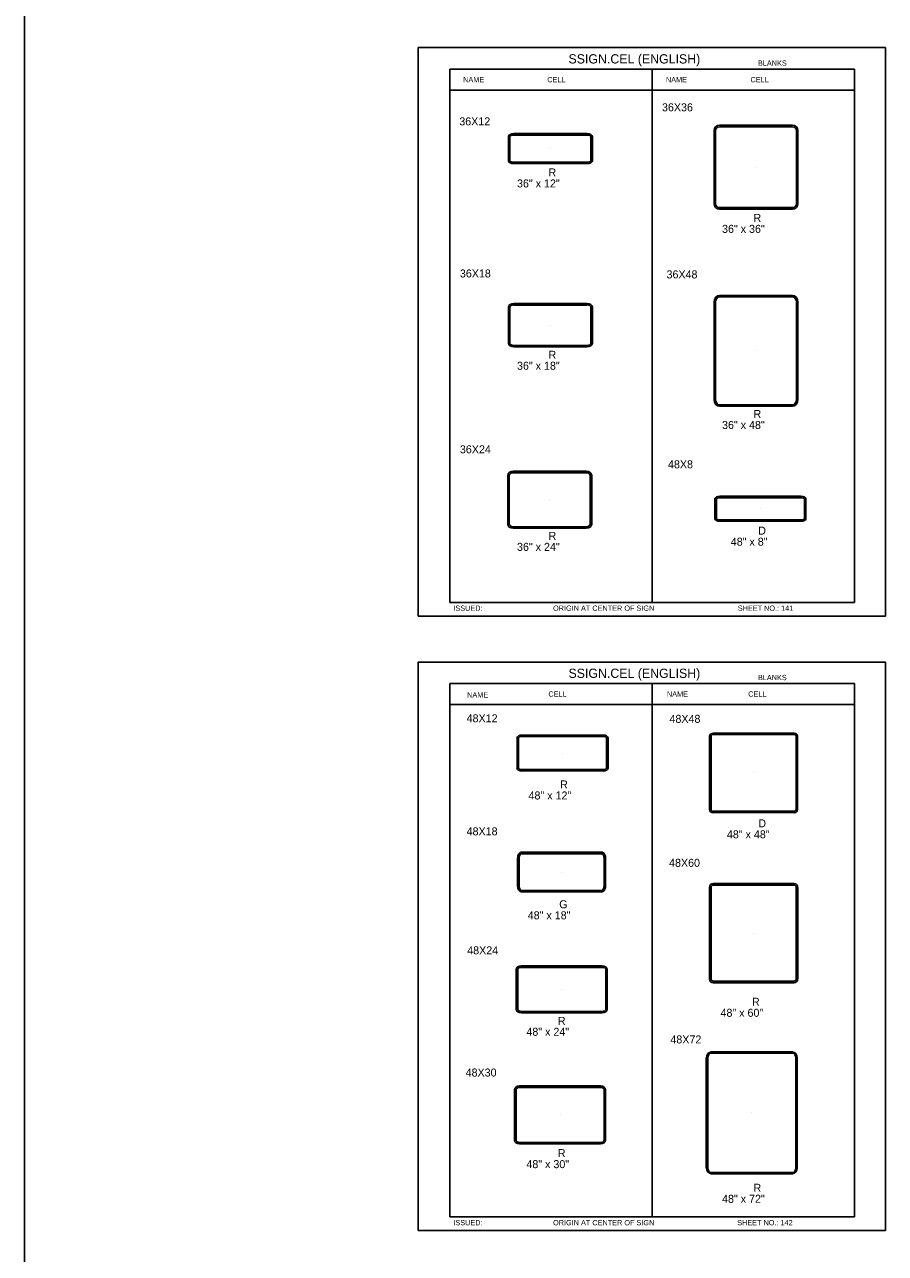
# Model space of a CAD drawing. Extents: x -5299 to 22597, y -19549 to -1808.
# Drawn here: x -218 to 1073, y -17521 to -15678 of the extents above; entities that cross this region are included whole.
import ezdxf

# ---------------------------------------------------------------- set-up
doc = ezdxf.new("R2010")
doc.units = 0
for name, color, linetype in [('Level 1', 7, 'Continuous'), ('Level 2', 7, 'Continuous'), ('Level 3', 7, 'Continuous'), ('Level 60', 7, 'Continuous')]:
    doc.layers.add(name, color=color, linetype=linetype)

msp = doc.modelspace()

# ---------------------------------------------------------------- linework, layer by layer
at = {"layer": 'Level 1'}
for p, q in [((1026.8, -15744.9), (419.8, -15744.9)), ((419.8, -15744.9), (419.8, -16544.9)), ((723.3, -15744.9), (723.3, -16544.9)), ((1026.8, -15744.9), (1026.8, -16544.9)), ((1026.8, -15776.5), (419.8, -15776.5)), ((570.7, -15864.2), (570.7, -15864.2)), ((879.1, -15892), (879.1, -15892)), ((570.7, -16129), (570.7, -16129)), ((879.1, -16167.5), (879.1, -16167.5)), ((569.7, -16390.8), (569.7, -16390.8)), ((885.8, -16404.3), (885.8, -16404.3)), ((419.8, -16544.9), (1026.8, -16544.9)), ((1026.8, -16666.3), (419.8, -16666.3)), ((419.8, -16666.3), (419.8, -17466.3)), ((723.3, -16666.3), (723.3, -17466.3)), ((1026.8, -16666.3), (1026.8, -17466.3)), ((1026.8, -16697.9), (419.8, -16697.9)), ((588.9, -16770.6), (588.9, -16770.6)), ((875.5, -16800.4), (875.5, -16800.4)), ((587.5, -16949), (587.5, -16949)), ((875.6, -17040.7), (875.6, -17040.7)), ((587.7, -17125), (587.7, -17125)), ((585.1, -17313.3), (585.1, -17313.3)), ((872.9, -17310.1), (872.9, -17310.1)), ((419.8, -17466.3), (1026.8, -17466.3))]:
    msp.add_line(p, q, dxfattribs=at)
at = {"layer": 'Level 3'}
for p, q in [((-218.2, -11251.9), (-218.2, -19549.4)), ((933.9, -15829.1), (824.3, -15829.1)), ((507.8, -15845.9), (507.8, -15882.5)), ((510, -15845.9), (510, -15882.5)), ((625.5, -15841.7), (515.9, -15841.7)), ((625.5, -15844), (515.9, -15844)), ((631.4, -15882.5), (631.4, -15845.9)), ((633.6, -15882.5), (633.6, -15845.9)), ((816.2, -15837.2), (816.2, -15946.8)), ((818.4, -15837.2), (818.4, -15946.8)), ((933.9, -15831.3), (824.3, -15831.3)), ((939.9, -15946.8), (939.9, -15837.2)), ((942.1, -15946.8), (942.1, -15837.2)), ((515.9, -15884.4), (625.5, -15884.4)), ((515.9, -15886.7), (625.5, -15886.7)), ((824.3, -15952.7), (933.9, -15952.7)), ((824.3, -15954.9), (933.9, -15954.9)), ((933.9, -16084.3), (824.3, -16084.3)), ((933.9, -16086.5), (824.3, -16086.5)), ((507.8, -16101.6), (507.8, -16156.4)), ((510, -16101.6), (510, -16156.4)), ((625.5, -16096.5), (515.9, -16096.5)), ((625.5, -16098.7), (515.9, -16098.7)), ((631.4, -16156.4), (631.4, -16101.6)), ((633.6, -16156.4), (633.6, -16101.6)), ((816.2, -16094.4), (816.2, -16240.5)), ((818.4, -16094.4), (818.4, -16240.5)), ((939.9, -16240.5), (939.9, -16094.4)), ((942.1, -16240.5), (942.1, -16094.4)), ((515.9, -16159.4), (625.5, -16159.4)), ((515.9, -16161.6), (625.5, -16161.6)), ((824.3, -16248.4), (933.9, -16248.4)), ((824.3, -16250.6), (933.9, -16250.6)), ((506.7, -16354.2), (506.7, -16427.3)), ((508.9, -16354.2), (508.9, -16427.3)), ((624.5, -16348.1), (514.8, -16348.1)), ((624.5, -16350.3), (514.8, -16350.3)), ((630.4, -16427.3), (630.4, -16354.2)), ((632.6, -16427.3), (632.6, -16354.2)), ((817.6, -16389.1), (817.6, -16419.5)), ((819.8, -16389.1), (819.8, -16419.5)), ((946.6, -16385.6), (825, -16385.6)), ((946.6, -16387.8), (825, -16387.8)), ((951.9, -16419.5), (951.9, -16389.1)), ((954.1, -16419.5), (954.1, -16389.1)), ((514.8, -16431.2), (624.5, -16431.2)), ((514.8, -16433.5), (624.5, -16433.5)), ((825, -16420.8), (946.6, -16420.8)), ((825, -16423), (946.6, -16423)), ((520.6, -16747.8), (520.6, -16793.4)), ((522.8, -16747.8), (522.8, -16793.4)), ((649.7, -16743.6), (528, -16743.6)), ((649.7, -16745.8), (528, -16745.8)), ((654.9, -16793.4), (654.9, -16747.8)), ((657.1, -16793.4), (657.1, -16747.8)), ((809.5, -16745.5), (809.5, -16855.3)), ((811.7, -16745.5), (811.7, -16855.3)), ((936.3, -16740.8), (814.7, -16740.8)), ((936.3, -16742.8), (814.7, -16742.8)), ((939.3, -16855.3), (939.3, -16745.5)), ((941.5, -16855.3), (941.5, -16745.5)), ((528, -16795.3), (649.7, -16795.3)), ((528, -16797.5), (649.7, -16797.5)), ((814.7, -16858), (936.3, -16858)), ((814.7, -16860), (936.3, -16860)), ((521.5, -16969), (521.5, -16929.1)), ((523.7, -16969), (523.7, -16929.1)), ((526.7, -16919.4), (648.3, -16919.4)), ((526.7, -16921.6), (648.3, -16921.6)), ((651.3, -16929.1), (651.3, -16969)), ((653.5, -16929.1), (653.5, -16969)), ((809.6, -16972.1), (809.6, -17109.3)), ((811.8, -16972.1), (811.8, -17109.3)), ((936.4, -16966.2), (814.8, -16966.2)), ((936.4, -16968.7), (814.8, -16968.7)), ((939.5, -17109.3), (939.5, -16972.1)), ((941.7, -17109.3), (941.7, -16972.1)), ((648.3, -16976.5), (526.7, -16976.5)), ((648.3, -16978.7), (526.7, -16978.7)), ((519.5, -17094.6), (519.5, -17155.4)), ((521.7, -17094.6), (521.7, -17155.4)), ((648.5, -17089.8), (526.9, -17089.8)), ((648.5, -17092), (526.9, -17092)), ((653.7, -17155.4), (653.7, -17094.6)), ((655.9, -17155.4), (655.9, -17094.6)), ((814.8, -17112.7), (936.4, -17112.7)), ((814.8, -17115.1), (936.4, -17115.1)), ((526.9, -17158), (648.5, -17158)), ((526.9, -17160.2), (648.5, -17160.2)), ((804.6, -17227.8), (804.6, -17392.4)), ((806.8, -17227.8), (806.8, -17392.4)), ((933.7, -17218.7), (812.1, -17218.7)), ((933.7, -17220.7), (812.1, -17220.7)), ((938.9, -17392.4), (938.9, -17227.8)), ((941.1, -17392.4), (941.1, -17227.8)), ((516.9, -17275.3), (516.9, -17351.3)), ((519.1, -17275.3), (519.1, -17351.3)), ((646, -17269.8), (524.3, -17269.8)), ((646, -17272.1), (524.3, -17272.1)), ((651.2, -17351.3), (651.2, -17275.3)), ((653.4, -17351.3), (653.4, -17275.3)), ((524.3, -17354.6), (646, -17354.6)), ((524.3, -17356.8), (646, -17356.8)), ((812.1, -17399.5), (933.7, -17399.5)), ((812.1, -17401.5), (933.7, -17401.5))]:
    msp.add_line(p, q, dxfattribs=at)
for centre, radius, start, end in [((824.3, -15837.2), 8.12, 90, 180), ((933.9, -15837.2), 8.12, 0, 90), ((824.3, -15837.2), 5.91, 90, 180), ((933.9, -15837.2), 5.91, 0, 90), ((824.3, -15946.8), 8.12, 180, 270), ((824.3, -15946.8), 5.91, 180, 270), ((933.9, -15946.8), 5.91, 270, 0), ((933.9, -15946.8), 8.12, 270, 0)]:
    msp.add_arc(centre, radius, start, end, dxfattribs=at)
for centre, major_axis, ratio, start_param, end_param in [((515.9, -15845.9), (-8.12, 0), 0.514853, 4.712389, 6.283185), ((515.9, -15845.9), (-5.91, 0), 0.333333, 4.712389, 6.283185), ((625.5, -15845.9), (-8.12, 0), 0.514853, 3.141593, 4.712389), ((625.5, -15845.9), (-5.91, 0), 0.333333, 3.141593, 4.712389), ((515.9, -15882.5), (8.12, 0), 0.514853, 3.141593, 4.712389), ((515.9, -15882.5), (5.91, 0), 0.333333, 3.141593, 4.712389), ((625.5, -15882.5), (5.91, 0), 0.333333, 4.712389, 6.283185), ((625.5, -15882.5), (8.12, 0), 0.514853, 4.712389, 6.283185), ((824.3, -16094.4), (0, -10.1), 0.804782, 3.141593, 4.712389), ((824.3, -16094.4), (0, -7.88), 0.75, 3.141593, 4.712389), ((933.9, -16094.4), (0, 10.1), 0.804782, 4.712389, 6.283185), ((933.9, -16094.4), (0, 7.88), 0.75, 4.712389, 6.283185), ((515.9, -16101.6), (-8.12, 0), 0.63614, 4.712389, 6.283185), ((515.9, -16101.6), (-5.91, 0), 0.5, 4.712389, 6.283185), ((625.5, -16101.6), (-8.12, 0), 0.63614, 3.141593, 4.712389), ((625.5, -16101.6), (-5.91, 0), 0.5, 3.141593, 4.712389), ((515.9, -16156.4), (8.12, 0), 0.63614, 3.141593, 4.712389), ((515.9, -16156.4), (5.91, 0), 0.5, 3.141593, 4.712389), ((625.5, -16156.4), (5.91, 0), 0.5, 4.712389, 6.283185), ((625.5, -16156.4), (8.12, 0), 0.63614, 4.712389, 6.283185), ((824.3, -16240.5), (0, -10.1), 0.804782, 4.712389, 6.283185), ((824.3, -16240.5), (0, -7.88), 0.75, 4.712389, 6.283185), ((933.9, -16240.5), (0, 7.88), 0.75, 3.141593, 4.712389), ((933.9, -16240.5), (0, 10.1), 0.804782, 3.141593, 4.712389), ((514.8, -16354.2), (-8.12, 0), 0.757427, 4.712389, 6.283185), ((514.8, -16354.2), (-5.91, 0), 0.666667, 4.712389, 6.283185), ((624.5, -16354.2), (-8.12, 0), 0.757427, 3.141593, 4.712389), ((624.5, -16354.2), (-5.91, 0), 0.666667, 3.141593, 4.712389), ((825, -16389.1), (-7.43, 0), 0.473248, 4.712389, 6.283185), ((825, -16389.1), (-5.22, 0), 0.25, 4.712389, 6.283185), ((946.6, -16389.1), (-7.43, 0), 0.473248, 3.141593, 4.712389), ((946.6, -16389.1), (-5.22, 0), 0.25, 3.141593, 4.712389), ((825, -16419.5), (7.43, 0), 0.473248, 3.141593, 4.712389), ((825, -16419.5), (5.22, 0), 0.25, 3.141593, 4.712389), ((946.6, -16419.5), (5.22, 0), 0.25, 4.712389, 6.283185), ((946.6, -16419.5), (7.43, 0), 0.473248, 4.712389, 6.283185), ((514.8, -16427.3), (8.12, 0), 0.757427, 3.141593, 4.712389), ((514.8, -16427.3), (5.91, 0), 0.666667, 3.141593, 4.712389), ((624.5, -16427.3), (5.91, 0), 0.666667, 4.712389, 6.283185), ((624.5, -16427.3), (8.12, 0), 0.757427, 4.712389, 6.283185), ((528, -16747.8), (-7.43, 0), 0.56104, 4.712389, 6.283185), ((528, -16747.8), (-5.22, 0), 0.375, 4.712389, 6.283185), ((649.7, -16747.8), (-7.43, 0), 0.56104, 3.141593, 4.712389), ((649.7, -16747.8), (-5.22, 0), 0.375, 3.141593, 4.712389), ((814.7, -16745.5), (-5.22, 0), 0.9025, 4.712389, 6.283185), ((814.7, -16745.5), (-3.01, 0), 0.9025, 4.712389, 6.283185), ((936.3, -16745.5), (-5.22, 0), 0.9025, 3.141593, 4.712389), ((936.3, -16745.5), (-3.01, 0), 0.9025, 3.141593, 4.712389), ((528, -16793.4), (7.43, 0), 0.56104, 3.141593, 4.712389), ((528, -16793.4), (5.22, 0), 0.375, 3.141593, 4.712389), ((649.7, -16793.4), (5.22, 0), 0.375, 4.712389, 6.283185), ((649.7, -16793.4), (7.43, 0), 0.56104, 4.712389, 6.283185), ((814.7, -16855.3), (5.22, 0), 0.9025, 3.141593, 4.712389), ((814.7, -16855.3), (3.01, 0), 0.9025, 3.141593, 4.712389), ((936.3, -16855.3), (3.01, 0), 0.9025, 4.712389, 6.283185), ((936.3, -16855.3), (5.22, 0), 0.9025, 4.712389, 6.283185), ((526.7, -16929.1), (0, -9.73), 0.536402, 3.141593, 4.712389), ((526.7, -16929.1), (0, -7.52), 0.4, 3.141593, 4.712389), ((648.3, -16929.1), (0, 9.73), 0.536402, 4.712389, 6.283185), ((648.3, -16929.1), (0, 7.52), 0.4, 4.712389, 6.283185), ((526.7, -16969), (0, -9.73), 0.536402, 4.712389, 6.283185), ((526.7, -16969), (0, -7.52), 0.4, 4.712389, 6.283185), ((648.3, -16969), (0, 7.52), 0.4, 3.141593, 4.712389), ((648.3, -16969), (0, 9.73), 0.536402, 3.141593, 4.712389), ((814.8, -16972.1), (0, -5.89), 0.886427, 3.141593, 4.712389), ((814.8, -16972.1), (0, -3.39), 0.886427, 3.141593, 4.712389), ((936.4, -16972.1), (0, 5.89), 0.886427, 4.712389, 6.283185), ((936.4, -16972.1), (0, 3.39), 0.886427, 4.712389, 6.283185), ((526.9, -17094.6), (-7.43, 0), 0.648832, 4.712389, 6.283185), ((526.9, -17094.6), (-5.22, 0), 0.5, 4.712389, 6.283185), ((648.5, -17094.6), (-7.43, 0), 0.648832, 3.141593, 4.712389), ((648.5, -17094.6), (-5.22, 0), 0.5, 3.141593, 4.712389), ((814.8, -17109.3), (0, -5.89), 0.886427, 4.712389, 6.283185), ((814.8, -17109.3), (0, -3.39), 0.886427, 4.712389, 6.283185), ((936.4, -17109.3), (0, 3.39), 0.886427, 3.141593, 4.712389), ((936.4, -17109.3), (0, 5.89), 0.886427, 3.141593, 4.712389), ((526.9, -17155.4), (7.43, 0), 0.648832, 3.141593, 4.712389), ((526.9, -17155.4), (5.22, 0), 0.5, 3.141593, 4.712389), ((648.5, -17155.4), (5.22, 0), 0.5, 4.712389, 6.283185), ((648.5, -17155.4), (7.43, 0), 0.648832, 4.712389, 6.283185), ((812.1, -17227.8), (0, -9.06), 0.820056, 3.141593, 4.712389), ((812.1, -17227.8), (0, -7.07), 0.738689, 3.141593, 4.712389), ((933.7, -17227.8), (0, 9.06), 0.820056, 4.712389, 6.283185), ((933.7, -17227.8), (0, 7.07), 0.738689, 4.712389, 6.283185), ((524.3, -17275.3), (-7.43, 0), 0.736624, 4.712389, 6.283185), ((524.3, -17275.3), (-5.22, 0), 0.625, 4.712389, 6.283185), ((646, -17275.3), (-7.43, 0), 0.736624, 3.141593, 4.712389), ((646, -17275.3), (-5.22, 0), 0.625, 3.141593, 4.712389), ((524.3, -17351.3), (7.43, 0), 0.736624, 3.141593, 4.712389), ((524.3, -17351.3), (5.22, 0), 0.625, 3.141593, 4.712389), ((646, -17351.3), (5.22, 0), 0.625, 4.712389, 6.283185), ((646, -17351.3), (7.43, 0), 0.736624, 4.712389, 6.283185), ((812.1, -17392.4), (0, -9.06), 0.820056, 4.712389, 6.283185), ((812.1, -17392.4), (0, -7.07), 0.738689, 4.712389, 6.283185), ((933.7, -17392.4), (0, 7.07), 0.738689, 3.141593, 4.712389), ((933.7, -17392.4), (0, 9.06), 0.820056, 3.141593, 4.712389)]:
    msp.add_ellipse(centre, major_axis=major_axis, ratio=ratio, start_param=start_param, end_param=end_param, dxfattribs=at)
at = {"layer": 'Level 60'}
for points in [[(372.3, -16565.1), (1073.3, -16565.1), (1073.3, -15712.7), (372.3, -15712.7)], [(372.3, -17486.5), (1073.3, -17486.5), (1073.3, -16634.1), (372.3, -16634.1)]]:
    msp.add_lwpolyline(points, close=True, dxfattribs=at)

# ---------------------------------------------------------------- texts
at = {"layer": 'Level 2'}
for s, p in [('36X36', (738.1, -15808.2)), ('36X12', (434, -15829.3)), ('36X18', (434.9, -16057.4)), ('36X48', (744.9, -16058.8)), ('36X24', (434.9, -16321.1)), ('48X8', (747.1, -16343.6)), ('48X12', (445, -16724.5)), ('48X48', (749.3, -16725.3)), ('48X18', (445, -16894)), ('48X60', (748.7, -16941.2)), ('48X24', (445.9, -17072.5)), ('48X72', (750.7, -17206.1)), ('48X30', (443.5, -17255.7))]:
    msp.add_text(s, height=12, dxfattribs=at).set_placement(p)
at = {"layer": 'Level 3'}
for s, height, p in [('SSIGN.CEL (ENGLISH)', 13.857, (597.8, -15736.5)), ('BLANKS', 7.92, (882.1, -15739.9)), ('NAME', 7.92, (439.8, -15764.7)), ('CELL', 7.92, (566, -15764.7)), ('NAME', 7.92, (744, -15764.7)), ('CELL', 7.92, (870.9, -15764.7)), ('R', 12, (567.9, -15905.9)), ('36" x 12"', 12, (520.6, -15922.4)), ('R', 12, (875.4, -15974.1)), ('36" x 36"', 12, (828.2, -15990.5)), ('R', 12, (567.9, -16179.3)), ('36" x 18"', 12, (520.6, -16195.8)), ('R', 12, (875.4, -16268.1)), ('36" x 48"', 12, (828.2, -16284.6)), ('D', 12, (882.5, -16443.1)), ('36" x 24"', 12, (520.6, -16467.4)), ('R', 12, (567.9, -16450.9)), ('48" x 8"', 12, (841.3, -16459.6)), ('ISSUED:', 7.92, (425.1, -16557.3)), ('ORIGIN AT CENTER OF SIGN', 7.918, (574.7, -16557.3)), ('SHEET NO.: 141', 7.918, (851.8, -16557.3)), ('SSIGN.CEL (ENGLISH)', 13.857, (597.8, -16657.9)), ('BLANKS', 7.92, (882.1, -16661.3)), ('NAME', 7.92, (445.8, -16687.3)), ('CELL', 7.92, (567.7, -16686.1)), ('NAME', 7.92, (745.5, -16686.1)), ('CELL', 7.92, (867.5, -16686.1)), ('R', 12, (585.2, -16823.7)), ('48" x 12"', 12, (537.9, -16840.2)), ('D', 12, (882.6, -16882)), ('48" x 48"', 12, (835.5, -16898.5)), ('48" x 18"', 12, (536.7, -17019.9)), ('G', 12, (583.9, -17003.4)), ('R', 12, (873.1, -17149.6)), ('48" x 60"', 12, (825.9, -17166.1)), ('R', 12, (581.9, -17178.2)), ('48" x 24"', 12, (534.7, -17194.6)), ('R', 12, (581.9, -17376.6)), ('48" x 30"', 12, (534.7, -17393.1)), ('48" x 72"', 12, (828.2, -17445.1)), ('R', 12, (875.4, -17428.6)), ('ISSUED:', 7.92, (425.1, -17478.8)), ('ORIGIN AT CENTER OF SIGN', 7.918, (574.7, -17478.8)), ('SHEET NO.: 142', 7.918, (850.9, -17478.8))]:
    msp.add_text(s, height=height, dxfattribs=at).set_placement(p)

doc.saveas('drawing.dxf')
